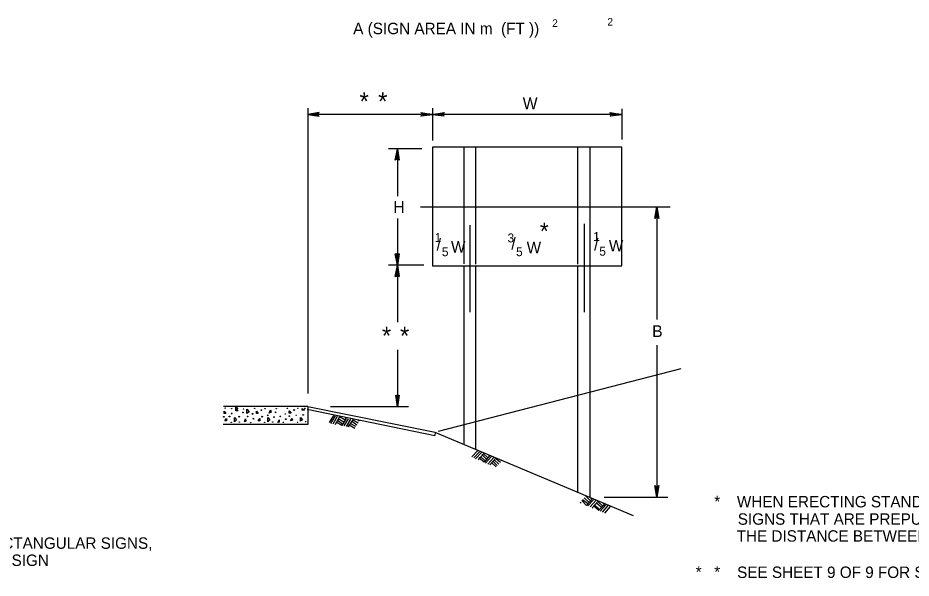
# Model space of a CAD drawing. Extents: x 644358 to 648627, y 294594 to 295782.
# Drawn here: x 645519 to 645753.8, y 294895.9 to 295043.1 of the extents above; entities that cross this region are included whole.
import ezdxf

# ---------------------------------------------------------------- set-up
doc = ezdxf.new("R2010")
doc.units = 0
for name, color, linetype in [('1', 7, 'Continuous'), ('2', 7, 'Continuous'), ('3', 7, 'Continuous'), ('4', 7, 'Continuous')]:
    doc.layers.add(name, color=color, linetype=linetype)

msp = doc.modelspace()

# ---------------------------------------------------------------- linework, layer by layer
at = {"layer": '1'}
for p, q in [((645627.94, 294977.98), (645627.94, 294977.98)), ((645601.94, 294938.6), (645600.81, 294936.73)), ((645602.44, 294938.48), (645601.19, 294936.48)), ((645602.94, 294938.35), (645601.81, 294936.35)), ((645603.56, 294938.23), (645602.44, 294936.23)), ((645604.31, 294936.35), (645602.94, 294937.35)), ((645604.69, 294936.85), (645603.19, 294937.73)), ((645605.06, 294937.35), (645603.56, 294938.23)), ((645605.31, 294937.85), (645604.19, 294935.98)), ((645605.81, 294937.73), (645604.69, 294935.85)), ((645605.31, 294937.73), (645605.06, 294937.98)), ((645606.44, 294937.6), (645605.31, 294935.73)), ((645607.06, 294937.48), (645605.69, 294935.6)), ((645608.06, 294936.1), (645606.69, 294937.1)), ((645608.44, 294936.6), (645606.94, 294937.48)), ((645608.69, 294937.1), (645608.44, 294937.35)), ((645602.69, 294936.23), (645602.44, 294936.35)), ((645604.19, 294935.98), (645602.69, 294936.85)), ((645606.06, 294935.6), (645605.69, 294935.73)), ((645607.56, 294935.23), (645606.06, 294936.1)), ((645607.81, 294935.73), (645606.31, 294936.48)), ((645639.81, 294929.35), (645638.31, 294927.73)), ((645640.31, 294929.1), (645638.81, 294927.48)), ((645640.81, 294928.85), (645639.31, 294927.23)), ((645641.44, 294928.6), (645639.94, 294926.98)), ((645641.81, 294926.73), (645640.56, 294927.85)), ((645642.19, 294927.1), (645640.94, 294928.35)), ((645642.56, 294927.48), (645641.31, 294928.6)), ((645643.06, 294928.1), (645641.56, 294926.35)), ((645643.44, 294927.85), (645641.94, 294926.1)), ((645642.94, 294927.98), (645642.81, 294928.23)), ((645640.19, 294926.98), (645639.94, 294927.1)), ((645641.56, 294926.35), (645640.19, 294927.48)), ((645644.06, 294927.6), (645642.56, 294925.85)), ((645644.56, 294927.35), (645643.06, 294925.6)), ((645643.19, 294925.6), (645643.19, 294925.73)), ((645644.69, 294925.1), (645643.44, 294926.23)), ((645644.94, 294925.48), (645643.81, 294926.6)), ((645645.44, 294925.85), (645644.19, 294926.98)), ((645645.81, 294926.23), (645644.56, 294927.35)), ((645646.19, 294926.73), (645645.94, 294926.85)), ((645668.44, 294914.98), (645667.19, 294916.23)), ((645668.69, 294915.48), (645667.44, 294916.48)), ((645669.06, 294915.85), (645667.81, 294916.98)), ((645669.44, 294916.23), (645668.19, 294917.48)), ((645669.94, 294916.6), (645668.44, 294914.98)), ((645670.31, 294916.48), (645668.81, 294914.85)), ((645670.94, 294916.23), (645669.44, 294914.6)), ((645669.81, 294916.6), (645669.69, 294916.85)), ((645671.44, 294915.98), (645669.94, 294914.35)), ((645672.69, 294914.85), (645671.44, 294915.98)), ((645667.06, 294915.6), (645666.81, 294915.85)), ((645670.19, 294914.23), (645670.06, 294914.35)), ((645671.69, 294913.6), (645670.31, 294914.85)), ((645671.81, 294913.98), (645670.56, 294915.1)), ((645672.31, 294914.48), (645671.06, 294915.6)), ((645673.19, 294915.23), (645671.56, 294913.6)), ((645673.56, 294915.1), (645672.06, 294913.48)), ((645674.06, 294914.98), (645672.56, 294913.23)), ((645673.06, 294915.23), (645672.81, 294915.48)), ((645674.69, 294914.73), (645673.19, 294912.98))]:
    msp.add_line(p, q, dxfattribs=at)
for points in [[(645598.06, 295018.1), (645597.94, 295017.85), (645595.19, 295017.73), (645598.06, 295018.1), (645598.19, 295018.23), (645595.19, 295017.73), (645597.94, 295017.6), (645598.06, 295017.35), (645595.19, 295017.73), (645598.19, 295017.23), (645598.06, 295017.35)], [(645625.06, 295018.1), (645625.19, 295017.85), (645627.94, 295017.73), (645625.06, 295018.1), (645624.94, 295018.23), (645627.94, 295017.73), (645625.19, 295017.6), (645625.06, 295017.35), (645627.94, 295017.73), (645624.94, 295017.23), (645625.06, 295017.35)], [(645630.94, 295017.35), (645630.81, 295017.6), (645627.94, 295017.73), (645630.94, 295017.35), (645631.06, 295017.23), (645627.94, 295017.73), (645630.81, 295017.85), (645630.94, 295018.1), (645627.94, 295017.73), (645631.06, 295018.23), (645630.94, 295018.1)], [(645674.69, 295018.1), (645674.81, 295017.85), (645677.69, 295017.73), (645674.69, 295018.1), (645674.69, 295018.23), (645677.69, 295017.73), (645674.81, 295017.6), (645674.81, 295017.35), (645677.69, 295017.73), (645674.69, 295017.23), (645674.81, 295017.35)], [(645618.31, 295005.85), (645618.56, 295005.98), (645618.81, 295008.73), (645618.31, 295005.85), (645618.19, 295005.73), (645618.81, 295008.73), (645618.94, 295005.98), (645619.19, 295005.85), (645618.81, 295008.73), (645619.19, 295005.73), (645619.19, 295005.85)], [(645686.56, 294990.6), (645686.69, 294990.73), (645686.94, 294993.48), (645686.56, 294990.6), (645686.44, 294990.35), (645686.94, 294993.48), (645687.06, 294990.73), (645687.31, 294990.6), (645686.94, 294993.48), (645687.44, 294990.35), (645687.31, 294990.6)], [(645619.19, 294981.1), (645618.94, 294980.98), (645618.81, 294978.1), (645619.19, 294981.1), (645619.19, 294981.1), (645618.81, 294978.1), (645618.56, 294980.98), (645618.44, 294981.1), (645618.81, 294978.1), (645618.19, 294981.1), (645618.44, 294981.1)], [(645618.31, 294975.1), (645618.56, 294975.23), (645618.81, 294978.1), (645618.31, 294975.1), (645618.19, 294975.1), (645618.81, 294978.1), (645618.94, 294975.23), (645619.19, 294975.1), (645618.81, 294978.1), (645619.19, 294975.1), (645619.19, 294975.1)], [(645619.19, 294943.85), (645618.94, 294943.73), (645618.81, 294940.85), (645619.19, 294943.85), (645619.19, 294943.98), (645618.81, 294940.85), (645618.69, 294943.73), (645618.44, 294943.85), (645618.81, 294940.85), (645618.31, 294943.98), (645618.44, 294943.85)], [(645687.31, 294919.98), (645687.06, 294919.98), (645686.94, 294917.1), (645687.31, 294919.98), (645687.44, 294920.23), (645686.94, 294917.1), (645686.69, 294919.98), (645686.69, 294919.98), (645686.94, 294917.1), (645686.44, 294920.23), (645686.69, 294919.98)]]:
    msp.add_lwpolyline(points, dxfattribs=at)
for points in [[(645573.19, 294939.1), (645573.19, 294939.73), (645573.69, 294939.1)], [(645576.31, 294939.98), (645576.31, 294940.98), (645576.81, 294940.48)], [(645576.31, 294939.85), (645576.31, 294940.48), (645576.94, 294939.85)], [(645579.19, 294939.1), (645579.19, 294940.23), (645579.81, 294939.6)], [(645581.69, 294939.1), (645581.69, 294939.73), (645582.19, 294939.1)], [(645585.44, 294940.1), (645585.56, 294939.48), (645585.06, 294939.23)], [(645590.31, 294939.23), (645590.31, 294939.85), (645590.81, 294939.23)], [(645593.69, 294939.98), (645593.69, 294940.48), (645594.31, 294939.98)], [(645573.81, 294937.85), (645573.81, 294937.23), (645573.44, 294937.23)], [(645575.94, 294936.98), (645575.94, 294938.1), (645576.44, 294937.48)], [(645578.81, 294937.73), (645578.94, 294937.1), (645578.56, 294936.98)], [(645582.56, 294937.85), (645582.56, 294937.23), (645582.19, 294937.23)], [(645584.69, 294936.98), (645584.69, 294938.1), (645585.19, 294937.48)], [(645587.69, 294937.48), (645587.69, 294936.85), (645587.31, 294936.73)], [(645591.06, 294937.85), (645591.19, 294937.35), (645590.69, 294937.23)], [(645593.31, 294937.1), (645593.31, 294938.1), (645593.81, 294937.48)]]:
    msp.add_lwpolyline(points, close=True, dxfattribs=at)
for centre, radius in [((645573.53, 294940.53), 0.056), ((645575.22, 294940.43), 0.056), ((645578.16, 294939.39), 0.0979), ((645578.31, 294940.34), 0.056), ((645581.26, 294940.46), 0.056), ((645583.01, 294940.01), 0.0979), ((645583.99, 294940.43), 0.056), ((645586.76, 294939.44), 0.0979), ((645586.91, 294940.39), 0.056), ((645589.86, 294940.51), 0.056), ((645591.6, 294940.06), 0.0979), ((645592.59, 294940.48), 0.056), ((645594.43, 294940.45), 0.056), ((645573.14, 294938.27), 0.0979), ((645574.64, 294938.34), 0.0979), ((645575.19, 294939.15), 0.0979), ((645577.17, 294938.31), 0.0979), ((645579.39, 294938.32), 0.0979), ((645580.69, 294939.07), 0.0979), ((645580.91, 294937.78), 0.0979), ((645583.19, 294938.29), 0.0979), ((645584.66, 294938.65), 0.0979), ((645586.32, 294938.16), 0.0979), ((645587.98, 294938.37), 0.0979), ((645589.27, 294939), 0.056), ((645589.41, 294937.65), 0.0979), ((645590.34, 294938.42), 0.0979), ((645592.15, 294938.67), 0.056), ((645593.99, 294938.75), 0.0979), ((645575.13, 294936.78), 0.056), ((645577.24, 294936.91), 0.056), ((645580.22, 294936.75), 0.056), ((645583.9, 294936.78), 0.056), ((645586.01, 294936.91), 0.056), ((645588.81, 294936.8), 0.056), ((645592.5, 294936.83), 0.056), ((645594.61, 294936.96), 0.056)]:
    msp.add_circle(centre, radius, dxfattribs=at)
at = {"layer": '2'}
for p, q in [((645627.94, 295009.1), (645627.94, 294977.98)), ((645677.69, 295009.1), (645627.94, 295009.1)), ((645636.19, 295009.1), (645636.19, 294978.48)), ((645639.31, 295009.1), (645639.31, 294978.35)), ((645666.06, 295009.1), (645666.06, 294978.35)), ((645669.31, 295009.1), (645669.31, 294978.1)), ((645677.69, 294977.98), (645677.69, 295009.1)), ((645667.81, 294988.98), (645667.81, 294965.73)), ((645637.81, 294988.6), (645637.81, 294965.73)), ((645627.94, 294977.98), (645627.94, 294977.98)), ((645627.94, 294977.98), (645677.69, 294977.98)), ((645627.94, 294977.98), (645627.94, 294977.98)), ((645636.19, 294977.85), (645636.19, 294930.98)), ((645637.81, 294977.98), (645637.81, 294977.98)), ((645639.31, 294977.98), (645639.31, 294929.73)), ((645666.06, 294977.98), (645666.06, 294918.35)), ((645667.81, 294977.98), (645667.81, 294977.98)), ((645669.31, 294977.85), (645669.31, 294917.1)), ((645677.31, 294977.98), (645677.31, 294977.98)), ((645629.56, 294934.48), (645693.31, 294950.98)), ((645595.19, 294940.98), (645573.06, 294940.98)), ((645595.06, 294940.23), (645628.56, 294933.35)), ((645595.19, 294940.98), (645628.69, 294934.23)), ((645595.19, 294940.98), (645595.19, 294936.23)), ((645595.19, 294936.23), (645572.94, 294936.23)), ((645628.56, 294934.23), (645680.69, 294912.35)), ((645628.69, 294934.23), (645628.56, 294933.35)), ((645628.69, 294934.23), (645628.56, 294933.35))]:
    msp.add_line(p, q, dxfattribs=at)
at = {"layer": '4'}
for p, q in [((645595.19, 295019.35), (645595.19, 294944.35)), ((645627.94, 295019.35), (645627.94, 295010.85)), ((645677.69, 295019.23), (645677.69, 295011.1)), ((645627.94, 295017.73), (645595.19, 295017.73)), ((645677.69, 295017.73), (645627.94, 295017.73)), ((645625.19, 295008.73), (645616.44, 295008.73)), ((645618.81, 295008.73), (645618.81, 294996.23)), ((645624.81, 294993.48), (645690.44, 294993.48)), ((645686.94, 294993.48), (645686.94, 294963.85)), ((645618.81, 294990.35), (645618.81, 294978.1)), ((645625.69, 294978.1), (645616.44, 294978.1)), ((645618.81, 294978.1), (645618.81, 294963.1)), ((645618.81, 294955.85), (645618.81, 294940.85)), ((645686.94, 294957.1), (645686.94, 294917.1)), ((645621.69, 294940.85), (645601.19, 294940.85)), ((645689.81, 294917.1), (645673.06, 294917.1))]:
    msp.add_line(p, q, dxfattribs=at)

# ---------------------------------------------------------------- texts
at = {"layer": '3'}
msp.add_text('SEE SHEET 9 OF 9 FOR SIGN LOCATION/INSTALLATION', height=3, dxfattribs=at).set_placement((645708.03, 294895.91))
at = {"layer": '4'}
for s, height, p in [('2', 2, (645659.43, 295040.71)), ('2', 2, (645673.92, 295041.08)), ('A (SIGN AREA IN m  (FT ))', 3.005, (645607.14, 295038.82)), ('*', 4.68, (645608.81, 295018.85)), ('*', 4.68, (645613.69, 295018.85)), ('W', 3.09, (645651.69, 295019.1)), ('H', 3.09, (645617.69, 294991.85)), ('*', 4.45, (645656.19, 294984.85)), ('1', 2.34, (645628.56, 294984.23)), ('3', 2.34, (645647.69, 294984.1)), ('1', 2.34, (645670.19, 294984.48)), ('/', 3.11, (645629.06, 294981.98)), ('W', 3, (645632.84, 294981.43)), ('/', 3.11, (645648.69, 294982.23)), ('W', 3, (645652.73, 294981.26)), ('/', 3.11, (645670.44, 294981.98)), ('W', 3, (645674.33, 294981.73)), ('5', 2.34, (645630.44, 294980.48)), ('5', 2.34, (645649.94, 294980.48)), ('5', 2.34, (645671.81, 294980.6)), ('*', 4.68, (645614.69, 294957.23)), ('*', 4.68, (645619.44, 294957.23)), ('B', 3.09, (645685.69, 294959.23)), ('*', 3, (645702.02, 294914.5)), ('WHEN ERECTING STANDARD WARNING OR REGULATORY', 3, (645707.97, 294914.46)), ('SIGNS THAT ARE PREPUNCHED, THIS DISTANCE IS', 3, (645708.2, 294909.9)), ('A = W x H FOR SQUARE OR RECTANGULAR SIGNS,', 3, (645455.29, 294903.57)), ('THE DISTANCE BETWEEN THE HORIZONTAL HOLES.', 3, (645707.91, 294905.45)), ('              WHERE: W = WIDTH OF SIGN', 3, (645455.29, 294899.07)), ('*', 3, (645697.15, 294896)), ('*', 3, (645702.02, 294896))]:
    msp.add_text(s, height=height, dxfattribs=at).set_placement(p)

doc.saveas('drawing.dxf')
